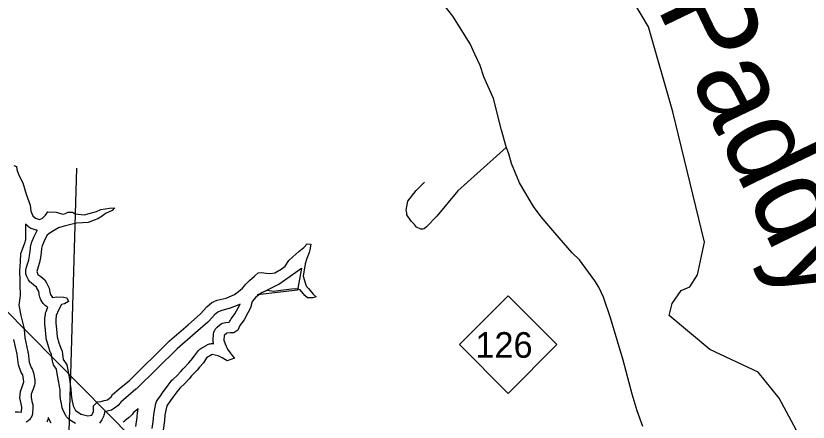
# Model space of a CAD drawing. Extents: x 1113032 to 1302912, y 664689 to 832535.
# Drawn here: x 1134389 to 1139798, y 742398 to 745173 of the extents above; entities that cross this region are included whole.
import ezdxf

# ---------------------------------------------------------------- set-up
doc = ezdxf.new("R2010")
doc.units = 0
for name, color, linetype in [('Exist Boundary Political CountyLine', 7, 'Continuous'), ('Exist Hydrographic Buffer Line', 7, 'Continuous'), ('Exist Hydrographic Creek Single Shore', 7, 'Continuous'), ('Exist Hydrographic Creek Single Shore Label', 7, 'Continuous'), ('Exist Hydrographic Lake Shore', 7, 'Continuous'), ('Exist Road Non-System Type 51', 7, 'Continuous'), ('Exist Road Primary NC Attributed', 7, 'Continuous'), ('Exist Road Primary NC Shield CELL', 7, 'Continuous'), ('Exist Road Primary NC Shield Number Label', 7, 'Continuous'), ('Map Preparation Longitude Latitude Lines', 7, 'Continuous')]:
    doc.layers.add(name, color=color, linetype=linetype)

msp = doc.modelspace()

# ---------------------------------------------------------------- linework, layer by layer
at = {"layer": 'Exist Boundary Political CountyLine'}
msp.add_lwpolyline([(1114483.4, 761940.5), (1121830, 755020.9), (1129762.4, 747574.8), (1131998.8, 745469.7), (1132534.3, 744969.6), (1136601.4, 740850.7), (1137713.1, 739712.4), (1140850.4, 736412.5), (1141222.5, 736061.4), (1141222.5, 736061.4), (1142712.2, 734629.3), (1146816.8, 730669.7), (1148404.8, 729149.7)], dxfattribs=at)
at = {"layer": 'Exist Hydrographic Buffer Line'}
for points in [[(1134795.8, 742389.2), (1134756.3, 742414.1), (1134748.5, 742419.9), (1134741.4, 742426.6), (1134735.2, 742434.1), (1134730.1, 742442.4), (1134713.5, 742473.7), (1134709.1, 742483.8), (1134706.2, 742494.3), (1134697.6, 742538), (1134697.2, 742539.8), (1134696.9, 742541.6), (1134691.9, 742575.7), (1134691.4, 742580.6), (1134691.1, 742585.5), (1134690.6, 742620.6), (1134686.8, 742639.5), (1134686.5, 742641.2), (1134686.2, 742642.9), (1134680.6, 742679.9), (1134672.1, 742729.5), (1134666.8, 742760.1), (1134651.5, 742782.3), (1134647.1, 742789.5), (1134643.5, 742797.2), (1134640.9, 742805.1), (1134639.1, 742813.4), (1134631.8, 742860.5), (1134627.2, 742870.5), (1134625.5, 742874.3), (1134624.1, 742878.2), (1134611.8, 742914.7), (1134611.4, 742915.9), (1134611, 742917.2), (1134598.4, 742959.7), (1134596.5, 742967.3), (1134595.5, 742975.1), (1134591.4, 743026.3), (1134588, 743067.9), (1134587.9, 743069), (1134587.9, 743070.1), (1134586.7, 743092.1), (1134586.7, 743098.5), (1134587.2, 743104.9), (1134590.9, 743135.7), (1134592.7, 743145.2), (1134595.6, 743154.5), (1134606.7, 743182.2), (1134606, 743182.5), (1134597.3, 743187.4), (1134589.4, 743193.4), (1134582.3, 743200.4), (1134576.2, 743208.2), (1134563.5, 743227.1), (1134559.9, 743233), (1134556.8, 743239.2), (1134554.4, 743245.7), (1134552.5, 743252.4), (1134548.5, 743270), (1134548.1, 743272.2), (1134547.7, 743274.4), (1134545.2, 743289.1), (1134532.9, 743313.6), (1134529.6, 743319), (1134511.8, 743333.8), (1134493.4, 743348.3), (1134486.2, 743354.7), (1134479.8, 743361.9), (1134474.5, 743370), (1134470.3, 743378.6), (1134462.3, 743397.9), (1134460.1, 743403.9), (1134458.4, 743410), (1134457.3, 743416.3), (1134456.6, 743422.7), (1134456.6, 743429), (1134457.1, 743435.4), (1134458.1, 743441.7), (1134459.6, 743447.9), (1134468.9, 743479.5), (1134469.4, 743481.1), (1134470, 743482.6), (1134478.3, 743507), (1134482.8, 743533.9), (1134482.9, 743534.6), (1134483, 743535.4), (1134488, 743562.4), (1134488.3, 743584), (1134489.1, 743593.4), (1134491, 743602.6), (1134496.4, 743622.6), (1134498.3, 743628.7), (1134500.8, 743634.6), (1134512.8, 743660.5), (1134532.6, 743703.1), (1134535.1, 743707.9), (1134533.6, 743708.2), (1134527, 743709.9), (1134499.9, 743718.4), (1134492.5, 743721.2), (1134485.3, 743724.8), (1134478.6, 743729.1), (1134472.4, 743734.1), (1134455.5, 743749.2), (1134454.1, 743689.2), (1134454.4, 743649.9), (1134454.1, 743642.5), (1134453.1, 743635.2), (1134451.3, 743628), (1134448.9, 743621), (1134438, 743594.3), (1134421.1, 743548.5), (1134417.5, 743494.1), (1134414.2, 743432.4), (1134415.8, 743366.4), (1134415.8, 743366.3), (1134415.8, 743366.2), (1134416.6, 743329.1), (1134416.6, 743329.1), (1134416.6, 743329.1), (1134417.9, 743272.6), (1134417.8, 743267.7), (1134417.5, 743262.9), (1134410.2, 743195.7), (1134423.1, 743125.3), (1134444.1, 743043.3), (1134445.4, 743036.8), (1134446.2, 743030.1), (1134450.3, 742972.8), (1134471.4, 742878.4), (1134472.1, 742874.4), (1134472.7, 742870.4), (1134479.8, 742806.3), (1134492.9, 742770.8), (1134499.6, 742760.1), (1134503.1, 742753.9), (1134506, 742747.4), (1134508.2, 742740.6), (1134509.8, 742733.7), (1134518.3, 742686.3), (1134519.4, 742677.1), (1134519.3, 742667.8), (1134518.1, 742658.6), (1134515.7, 742649.6), (1134506.8, 742622.5), (1134506.3, 742621), (1134505.7, 742619.4), (1134494.4, 742589.5), (1134492.6, 742569.2), (1134499, 742539.8), (1134504.1, 742517.8), (1134505.8, 742506.4), (1134505.7, 742494.8), (1134502.7, 742459.6), (1134501.8, 742452.3), (1134500.1, 742445.1), (1134497.7, 742438.2), (1134494.6, 742431.5), (1134491, 742425.1), (1134486.7, 742419.2), (1134481.8, 742413.6), (1134476.5, 742408.6), (1134470.6, 742404.2), (1134464.4, 742400.3), (1134457.8, 742397)], [(1135319.8, 742353.9), (1135328.4, 742417.7), (1135331.9, 742454.6), (1135332.4, 742458.6), (1135333.1, 742462.5), (1135345.7, 742524.1), (1135347.6, 742531.5), (1135350.3, 742538.6), (1135353.6, 742545.5), (1135357.7, 742551.9), (1135382.4, 742587.4), (1135383, 742588.3), (1135383.6, 742589.2), (1135428.2, 742649.4), (1135428.6, 742649.9), (1135429, 742650.4), (1135450.3, 742678.3), (1135454.8, 742683.6), (1135459.8, 742688.5), (1135489.8, 742715.4), (1135515.1, 742742.5), (1135531.4, 742762), (1135533.1, 742764), (1135534.8, 742765.9), (1135569.6, 742802.3), (1135583.7, 742819.7), (1135584.7, 742820.9), (1135585.7, 742822.1), (1135609.8, 742849.6), (1135628.9, 742877.9), (1135633.9, 742884.6), (1135639.7, 742890.7), (1135646.1, 742896.1), (1135653.1, 742900.7), (1135692.2, 742923.7), (1135698.3, 742927), (1135704.8, 742929.6), (1135711.5, 742931.7), (1135718.3, 742933.1), (1135725.2, 742933.9), (1135732.2, 742934), (1135739.2, 742933.5), (1135739.4, 742933.5), (1135738.2, 742937.8), (1135736.6, 742944.2), (1135735.6, 742950.8), (1135735.2, 742957.5), (1135735.3, 742964.1), (1135737.5, 742994.5), (1135738.4, 743001.8), (1135740, 743009.1), (1135742.3, 743016.1), (1135745.3, 743022.9), (1135748.9, 743029.3), (1135753.2, 743035.3), (1135758, 743040.9), (1135763.4, 743046), (1135781.4, 743061.6), (1135790.5, 743068.3), (1135800.5, 743073.5), (1135811.1, 743077.2), (1135822.2, 743079.3), (1135843.3, 743081.6), (1135846.9, 743081.9), (1135847.6, 743081.9), (1135849.6, 743086.8), (1135853.6, 743095), (1135858.5, 743102.7), (1135883.9, 743137.4), (1135907.7, 743179.7), (1135920.1, 743203.7), (1135920.3, 743204.6), (1135910.8, 743199.9), (1135851.9, 743176.1), (1135847.3, 743174.4), (1135842.7, 743173), (1135788.4, 743158.9), (1135768.6, 743150), (1135745.8, 743130.6), (1135705.7, 743086.4), (1135702.5, 743083.1), (1135699.2, 743080), (1135614.6, 743006.8), (1135489.9, 742898.1), (1135214.4, 742626.7), (1135211.8, 742624.3), (1135209.1, 742622), (1135155.8, 742578.5), (1135142.1, 742566.6), (1135106.2, 742535.2), (1135101.2, 742527.9), (1135094.7, 742519.6), (1135087, 742512.3), (1135062.9, 742492.5), (1135056.3, 742487.6), (1135049.2, 742483.5), (1135041.7, 742480.1), (1135033.9, 742477.7), (1135011, 742471.8), (1135010.2, 742471.6), (1135009.4, 742471.4), (1134994, 742467.8), (1134993.6, 742461.6), (1134992.2, 742453.2), (1134989.9, 742445), (1134986.6, 742437.2), (1134975, 742413.2), (1134970.7, 742405.5), (1134965.5, 742398.3), (1134959.5, 742391.8)], [(1135208.8, 742368.9), (1135217.1, 742430.5), (1135220.5, 742465.4), (1135220.6, 742466.8), (1135220.8, 742468.3), (1135221.3, 742472.2), (1135221.7, 742475.2), (1135222.2, 742478.1), (1135222.8, 742482), (1135223.1, 742483.5), (1135223.4, 742485), (1135224.4, 742489.8), (1135215.6, 742482.2), (1135190.7, 742460.3), (1135193.7, 742464.8), (1135191.4, 742461.6), (1135189, 742458.4), (1135182.5, 742450.1), (1135177.4, 742444.1), (1135171.9, 742438.5), (1135164.2, 742431.2), (1135161.3, 742428.5), (1135158.3, 742426), (1135134.2, 742406.1), (1135131.8, 742404.2), (1135129.4, 742402.3), (1135122.8, 742397.4)], [(1134631.2, 742389.9), (1134614.6, 742421.3), (1134612.7, 742424.9), (1134611.1, 742428.3), (1134610.8, 742426.6), (1134609.1, 742419.4), (1134607.7, 742414.1), (1134606.1, 742408.9), (1134603.7, 742402), (1134601.8, 742396.8)]]:
    msp.add_lwpolyline(points, dxfattribs=at)
at = {"layer": 'Exist Hydrographic Creek Single Shore'}
msp.add_lwpolyline([(1139750.9, 742280.4), (1139600.9, 742562.4), (1139455.9, 742739.2), (1139126.9, 742893.6), (1138849.9, 743125.6), (1138869.9, 743207.3), (1138930.9, 743298), (1138989.9, 743323), (1139041.9, 743404), (1139089.9, 743626.3), (1138874.9, 744516.8), (1138708.9, 745097.8), (1138557.8, 745353.6), (1138250.8, 745678.1), (1138187.8, 745820.5), (1138196.4, 746280.4)], dxfattribs=at)
at = {"layer": 'Exist Hydrographic Lake Shore'}
for points in [[(1134374.8, 744150.3), (1134392.7, 744143.9), (1134395.5, 744123.5), (1134409.2, 744083.8), (1134436.3, 744032.5), (1134460.4, 743955.5), (1134486.3, 743879.7), (1134491, 743838.9), (1134504, 743806.5), (1134522.4, 743790), (1134549.5, 743781.5), (1134570.4, 743791), (1134590.9, 743811.8), (1134608.6, 743834.4), (1134664.5, 743831.5), (1134708.9, 743818.4), (1134728.5, 743823.2), (1134743.8, 743833.1), (1134776.5, 743831), (1134793.3, 743820.9), (1134855.2, 743813.8), (1134889.3, 743823.3), (1134939.4, 743837.5), (1134969.7, 743849.4), (1135028.3, 743860.4), (1135062.2, 743862.3), (1135046.6, 743842.7), (1135000.9, 743823.3), (1134978.8, 743803.8), (1134949.1, 743787.1), (1134924.6, 743777.6), (1134882.3, 743762.1), (1134844.2, 743760.3), (1134803.3, 743756.8), (1134763.4, 743747.4), (1134718.1, 743737.2), (1134679.6, 743724.1), (1134657.2, 743712.2), (1134617.5, 743687.2), (1134600.6, 743671.6), (1134580.9, 743628.9), (1134568.8, 743602.9), (1134563.3, 743582.9), (1134562.9, 743554.9), (1134556.8, 743521.7), (1134551.3, 743488.6), (1134540.9, 743458.2), (1134531.5, 743426.6), (1134539.5, 743407.4), (1134559, 743392.1), (1134586.9, 743368.8), (1134598.4, 743350.3), (1134617.4, 743312.6), (1134621.7, 743286.6), (1134625.7, 743269), (1134638.4, 743250.1), (1134669.9, 743252.8), (1134716.7, 743251.8), (1134737.1, 743247), (1134749.7, 743221.6), (1134721.4, 743206.2), (1134700.1, 743201.9), (1134679.5, 743162.3)], [(1134666.2, 743032.3), (1134670.3, 742981.1), (1134682.9, 742938.6), (1134695.2, 742902.1), (1134704.3, 742882.5), (1134713.2, 742824.9), (1134737.8, 742789.1), (1134746, 742742.3), (1134754.6, 742691.8), (1134760.4, 742654.2), (1134765.5, 742628.6), (1134766.1, 742586.6), (1134771.1, 742552.5), (1134779.8, 742508.9), (1134796.4, 742477.5), (1134835.8, 742452.6), (1134880.6, 742441.2), (1134907.5, 742445.9), (1134919.1, 742469.9), (1134919, 742508.3), (1134945.9, 742537.4), (1134972.2, 742539.7), (1134992.3, 742544.4), (1135015.2, 742550.3), (1135039.3, 742570.2), (1135049.6, 742585.4), (1135092.8, 742623.1), (1135107.5, 742636), (1135161.8, 742680.1), (1135438.9, 742953.1), (1135565.4, 743063.4), (1135650.1, 743136.7), (1135693.5, 743184.6), (1135728.1, 743214), (1135763.4, 743229.9), (1135823.8, 743245.6), (1135882.7, 743269.5), (1135908.8, 743290.1), (1135937.3, 743314), (1135959.4, 743341.1), (1135984.7, 743365.8), (1136018.5, 743395.7), (1136042.7, 743418.4), (1136066.7, 743419.1), (1136098.1, 743414.6), (1136127.8, 743412.1), (1136157.7, 743417.1), (1136200.7, 743441.8), (1136227.5, 743463.3), (1136252.5, 743501.6), (1136279.9, 743526.7), (1136321.2, 743562.6), (1136354.1, 743591.2), (1136378.7, 743615.5), (1136403.7, 743612.9), (1136396, 743574.6), (1136390.8, 743555.9), (1136375.4, 743515.1), (1136363.6, 743479.9), (1136350.5, 743395.9), (1136367.4, 743343.1), (1136374.4, 743325.4), (1136386.5, 743310.6), (1136418.2, 743271.6), (1136439.8, 743252.7), (1136414.1, 743247.3), (1136379.4, 743247), (1136361.8, 743262.7), (1136329.2, 743301.6), (1136300, 743308.1), (1136270.5, 743306.3), (1136197.3, 743298.1), (1136147.1, 743291.1), (1136104.4, 743297.3), (1136071.5, 743283.9), (1136026.6, 743251.3), (1136001.3, 743222.5), (1135991.1, 743177.8), (1135973.8, 743144.2), (1135947.1, 743096.7), (1135919, 743058.4), (1135905.6, 743025.6), (1135877.1, 743007.4), (1135851.5, 743007), (1135830.3, 743004.7), (1135812.3, 742989.2), (1135810.1, 742958.8), (1135817.6, 742933.2), (1135835, 742896.3), (1135852.1, 742871), (1135866.3, 742852.1), (1135881.5, 742834.1), (1135831.5, 742817.1), (1135798, 742836.8), (1135769.6, 742850.5), (1135730.2, 742859), (1135691.1, 742836.1), (1135669.4, 742803.7), (1135642.1, 742772.6), (1135626, 742752.7)], [(1136039.2, 743268.3), (1136184.6, 743341.1), (1136339, 743450.2), (1136312.2, 743300.2), (1136039.2, 743268.3)], [(1134679.5, 743162.3), (1134665.3, 743126.7), (1134661.6, 743095.9), (1134662.8, 743073.9), (1134666.2, 743032.3)], [(1134385.6, 742468.9), (1134407.3, 742467.6), (1134428, 742465.9), (1134431, 742501.1), (1134425.8, 742523.5), (1134416.9, 742564.4), (1134420.6, 742606.4), (1134435.6, 742645.9), (1134444.5, 742673.1), (1134436, 742720.4), (1134425.2, 742737.6), (1134406.3, 742788.9), (1134398.2, 742862.1), (1134375.9, 742961.9)], [(1135626, 742752.7), (1135589, 742714), (1135571.4, 742692.9), (1135542.3, 742661.8), (1135509.8, 742632.7), (1135488.5, 742604.8), (1135443.9, 742544.5), (1135419.2, 742509.1), (1135406.6, 742447.5), (1135402.9, 742409.1), (1135394.1, 742343.9)]]:
    msp.add_lwpolyline(points, dxfattribs=at)
at = {"layer": 'Exist Road Non-System Type 51'}
msp.add_lwpolyline([(1137736.8, 744273.8), (1137406.4, 743978.6), (1137263.1, 743804.9), (1137193.1, 743732.8), (1137176.7, 743719.3), (1137168.4, 743715.6), (1137154.3, 743716.2), (1137124.7, 743728.9), (1137111.3, 743747.2), (1137088.1, 743770), (1137057.2, 743815), (1137057.8, 743827.1), (1137054.2, 743845.2), (1137065.9, 743906.7), (1137122.2, 743979.1), (1137177.8, 744037.7)], dxfattribs=at)
at = {"layer": 'Exist Road Primary NC Attributed'}
msp.add_lwpolyline([(1138669.5, 742368.6), (1138631.4, 742474.6), (1138597.4, 742589.3), (1138535.6, 742820.1), (1138448.8, 743110.6), (1138400.4, 743251.7), (1138370, 743319.8), (1138341.3, 743362.8), (1138237, 743505.7), (1138187.7, 743554.9), (1138068.7, 743690.2), (1137974.8, 743800.8), (1137923.7, 743869.8), (1137827.2, 744031.6), (1137771.8, 744164.9), (1137753.8, 744230.3), (1137737.7, 744271.5), (1137704.6, 744391.2), (1137649.1, 744607.9), (1137583.5, 744756), (1137559.8, 744834.9), (1137521.9, 744912.1), (1137489.5, 744982), (1137372.8, 745170.3), (1137288.7, 745279.2)], dxfattribs=at)
at = {"layer": 'Exist Road Primary NC Shield CELL'}
msp.add_lwpolyline([(1137417, 742927.2), (1137750, 743260.2), (1138083, 742927.2), (1137750, 742594.2)], close=True, dxfattribs=at)
at = {"layer": 'Map Preparation Longitude Latitude Lines'}
msp.add_lwpolyline([(1134465.8, 732567.8), (1134702.1, 740609.5), (1134805.7, 744131.8)], dxfattribs=at)

# ---------------------------------------------------------------- texts
at = {"layer": 'Exist Hydrographic Creek Single Shore Label'}
msp.add_text('Paddy', height=600, rotation=295.6173, dxfattribs=at).set_placement((1138760.9, 745234.9))
at = {"layer": 'Exist Road Primary NC Shield Number Label'}
msp.add_text('126', height=175, dxfattribs=at).set_placement((1137526.1, 742837.4))

doc.saveas('drawing.dxf')
